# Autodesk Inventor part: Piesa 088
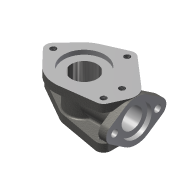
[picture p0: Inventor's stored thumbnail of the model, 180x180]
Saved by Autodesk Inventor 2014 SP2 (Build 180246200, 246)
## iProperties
Created: 2009-02
Part Number: Piesa 088
Document SubType Name: Modeling
Designer: Costel
Material: Steel, Cast
Density: 7.85 g/cm^3
Appearance: Steel - Cast
Author: Costel
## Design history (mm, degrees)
sketch "Sketch1"
  geometry: L1 (-79.482, 0)-(75.613, 0) reference; L2 (0, -41.972)-(0, 33.389) reference; L3 (0, 21)-(-47, 21); L4 (-51.223, 5.123)-(-10.432, -18.225); L5 (41.484, -28.864)-(-3.746, -20.663); L6 (30, 0)-(14.7, 14.997); L7 (30, 0)-(51.5, 0); L8 (51.5, 0)-(51.5, -20.5); A1 r 8.5 centre (-47, 12.5) between (-47, 21) and (-51.223, 5.123); A2 r 8.5 centre (43, -20.5) between (41.484, -28.864) and (51.5, -20.5); A3 r 21 centre (0, 0) between (-10.432, -18.225) and (-3.746, -20.663); A4 r 21 centre (0, 0) between (14.7, 14.997) and (0, 21)
  constraints: 12 end point, 8 point on circle, 8 tangent, 4 centre point, 2 parallel, 2 point on line, 1 collinear, 1 concentric, 1 vertical
  dimensions: "d1" = 8.5 radius of A1; "d2" = 47 distance from line of L2 A1.centre; "d3" = 8.5 radius of A2 (= d1); "d4" = 43 distance from line of L2 A2.centre; "d5" = 20.5 distance from line of L1 A2.centre; "d6" = 30 distance from line of L2 L6.start; "d7" = 21 radius of A4
extrude "Extrusion1" new body sketch "Sketch1" distance "d8" = 9; taper "d9" = 0 deg
sketch "Sketch2"
  geometry: A1 r 8.5 centre (-47, 12.5) between (-47, 21) and (-51.223, 5.123) reference; A2 r 8.5 centre (43, -20.5) between (41.484, -28.864) and (51.5, -20.5) reference
hole "Hole1" sketch "Sketch2" at (-47, 12.5), (43, -20.5) diameter "d10" = 8; stored, may be unused: countersink angle "d14" = 90 deg, drill point angle "d16" = 118 deg; dims "d11" = 6, "d12" = 4, "d13" = 2, "d15" = 8
sketch "Sketch3"
  geometry: L1 (51.5, 0)-(51.5, -20.5) reference; L2 (30, 0)-(51.5, 0) reference; L3 (14.7, 14.997)-(30, 0) reference; L4 (-47, 21)-(0, 21) reference; L5 (-10.432, -18.225)-(-51.223, 5.123) reference; L6 (41.484, -28.864)-(-3.746, -20.663) reference; C1 r 4 at (-47, 12.5) reference; C2 r 4 at (43, -20.5) reference; C3 r 19 at (0, 0); A1 r 8.5 centre (43, -20.5) between (41.484, -28.864) and (51.5, -20.5) reference; A2 r 21 centre (0, 0) between (14.7, 14.997) and (0, 21) reference; A3 r 8.5 centre (-47, 12.5) between (-47, 21) and (-51.223, 5.123) reference; A4 r 21 centre (0, 0) between (-10.432, -18.225) and (-3.746, -20.663) reference
  constraints: 1 centre point, 1 coincident
  dimensions: "d17" = 38 diameter of C3
extrude "Extrusion2" join sketch "Sketch3" distance "d18" = 49; taper "d19" = 0 deg
sketch "Sketch4"
  geometry: L1 (0, -54.195)-(0, 59.832) reference; L2 (-78.938, 0)-(85.128, 0) reference; L3 (-42.139, -5.879)-(-24.917, -23.862); L4 (4.557, -34.198)-(44.123, -28.926); L5 (50.751, -23.988)-(58.591, -6.565); L6 (54.467, 12.101)-(20.561, 41.429); L7 (11.578, 42.781)-(-13.889, 31.581); L8 (-42.139, 5.879)-(-24.917, 23.862); C1 r 19 at (0, 0) reference; A1 r 8.5 centre (-36, 0) between (-42.139, 5.879) and (-42.139, -5.879); A2 r 8.5 centre (15, 35) between (20.561, 41.429) and (11.578, 42.781); A3 r 8.5 centre (43, -20.5) between (44.123, -28.926) and (50.751, -23.988); A4 r 16 centre (44, 0) between (58.591, -6.565) and (54.467, 12.101); A5 r 34.5 centre (0, 0) between (-24.917, -23.862) and (4.557, -34.198); A6 r 34.5 centre (0, 0) between (-13.889, 31.581) and (-24.917, 23.862)
  constraints: 12 end point, 12 point on circle, 12 tangent, 6 centre point, 2 point on line, 1 coincident, 1 concentric
  dimensions: "d21" = 8.5 radius of A1; "d22" = 8.5 radius of A2 (= d21); "d23" = 8.5 radius of A3 (= d21); "d24" = 16 radius of A4; "d25" = 36 distance of A5.centre A1.centre; "d26" = 15 horizontal distance of A2.centre A5.centre; "d27" = 35 vertical distance of A1.centre A2.centre; "d28" = 44 distance of A5.centre A4.centre; "d29" = 43 horizontal distance of A5.centre A3.centre; "d30" = 20.5 vertical distance of A4.centre A3.centre; "d33" = 34.5 radius of A5
extrude "Extrusion3" join sketch "Sketch4" distance "d31" = 9; taper "d32" = 0 deg
sketch "Sketch5"
  geometry: A1 r 8.5 centre (-36, 0) between (-42.139, 5.879) and (-42.139, -5.879) reference; A2 r 8.5 centre (43, -20.5) between (44.123, -28.926) and (50.751, -23.988) reference; A3 r 8.5 centre (15, 35) between (20.561, 41.429) and (11.578, 42.781) reference
hole "Hole5" sketch "Sketch5" at (-36, 0), (43, -20.5), (15, 35) diameter "d73" = 6.647; stored, may be unused: countersink angle "d77" = 90 deg, drill point angle "d79" = 118 deg; dims "d74" = 6, "d75" = 4, "d76" = 2, "d78" = 8
hole "Hole3" diameter "d43" = 30; stored, may be unused: countersink angle "d47" = 90 deg, drill point angle "d49" = 118 deg; dims "d41" = 10, "d42" = 10, "d44" = 6, "d45" = 48, "d46" = 5, "d48" = 8
workplane "Work Plane1"
sketch "Sketch6"
  geometry: L1 (0, -9.8)-(0, 58.8) reference; L2 (-50.1, 0)-(59.1, 0) reference; C1 r 16 at (0, 24.5)
  constraints: 1 centre point, 1 midpoint
  dimensions: "d51" = 32 diameter of C1; "d52" = 24.5 distance from line of L2 C1.centre
extrude "Extrusion4" join sketch "Sketch6" stored distance "d53" = 9; taper "d54" = 0 deg
sketch "Sketch7"
  geometry: L1 (0, -9.8)-(0, 58.8) reference; L2 (-30.6, 32.785)-(-13.44, 44.384); L3 (-30.6, 16.215)-(-13.44, 4.616); L4 (30.6, 32.785)-(13.44, 44.384); L5 (30.6, 16.215)-(13.44, 4.616); C1 r 4 at (-25, 24.5); C2 r 4 at (25, 24.5); A1 r 16 centre (0, 24.5) between (15.62, 27.966) and (16, 24.5) reference; A2 r 10 centre (25, 24.5) between (30.6, 16.215) and (30.6, 32.785); A3 r 10 centre (-25, 24.5) between (-30.6, 32.785) and (-30.6, 16.215); A4 r 16 centre (0, 24.5) between (16, 24.5) and (15.62, 27.966); A5 r 24 centre (0, 24.5) between (13.44, 44.384) and (-13.44, 44.384); A6 r 24 centre (0, 24.5) between (-13.44, 4.616) and (13.44, 4.616)
  constraints: 12 point on circle, 8 end point, 7 centre point, 6 tangent, 4 coincident, 3 symmetric about line, 2 equal radius, 1 horizontal alignment
  dimensions: "d56" = 50 distance of A2.centre A3.centre; "d57" = 10 radius of A3; "d58" = 8 diameter of C1; "d61" = 24 radius of A5
extrude "Extrusion5" join sketch "Sketch7" distance "d62" = 9; taper "d63" = 0 deg
hole "Hole4" diameter "d66" = 24; stored, may be unused: countersink angle "d70" = 90 deg, drill point angle "d72" = 118 deg; dims "d64" = 10, "d65" = 10, "d67" = 6, "d68" = 36, "d69" = 5, "d71" = 8
sketch "Sketch8"
  geometry: A1 r 16 centre (44, 0) between (58.591, -6.565) and (54.467, 12.101) reference
hole "Hole6" sketch "Sketch8" at (44, 0) diameter "d84" = 6.647; stored, may be unused: countersink angle "d88" = 90 deg, drill point angle "d90" = 118 deg; dims "d85" = 6, "d86" = 4, "d87" = 2, "d89" = 10
fillet "Fillet1" dims "d80" = 2
fillet "Fillet2" dims "d81" = 2
fillet "Fillet3" dims "d82" = 2
fillet "Fillet4" dims "d83" = 2
body "Solid1"
node "Projected Loop1"
other parameters: "d50" = 60.5
